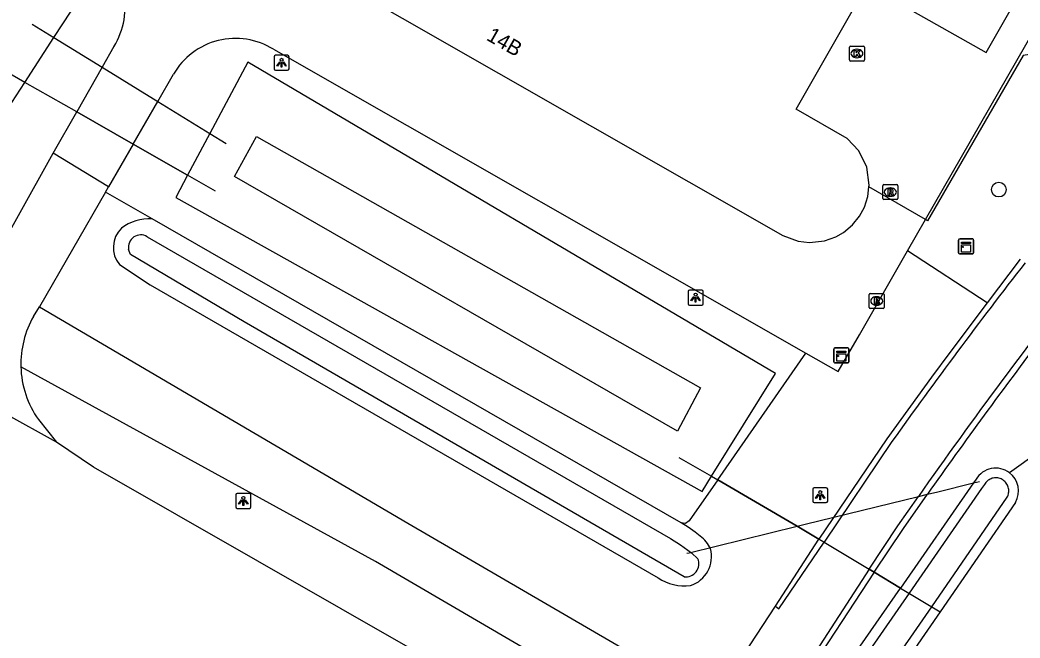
# Model space of a CAD drawing. Extents: x 157154 to 159278, y 385000 to 386650.
# Drawn here: x 158011.3 to 158077.8, y 385589.4 to 385630.5 of the extents above; entities that cross this region are included whole.
import ezdxf

# ---------------------------------------------------------------- set-up
doc = ezdxf.new("R2010")
doc.units = 0
for name, color, linetype in [('IMGEO_Boom', 7, 'Continuous'), ('IMGEO_Duiker', 7, 'Continuous'), ('IMGEO_Gemengd_bos', 7, 'Continuous'), ('IMGEO_Groenvoorziening', 7, 'Continuous'), ('IMGEO_Hek', 7, 'Continuous'), ('IMGEO_Kast', 7, 'Continuous'), ('IMGEO_Kolk', 7, 'Continuous'), ('IMGEO_Lichtpunt', 7, 'Continuous'), ('IMGEO_Pand', 7, 'Continuous'), ('IMGEO_Pand_nummerreeks', 7, 'Continuous'), ('IMGEO_Rijbaan_lokaal_gesloten', 7, 'Continuous'), ('IMGEO_Rijbaan_lokaal_open', 7, 'Continuous'), ('IMGEO_Rioolput', 7, 'Continuous'), ('IMGEO_Voetpad_halfverhard', 7, 'Continuous'), ('IMGEO_Waterloop', 7, 'Continuous')]:
    doc.layers.add(name, color=color, linetype=linetype)

msp = doc.modelspace()

# ---------------------------------------------------------------- linework, layer by layer
at = {"layer": 'IMGEO_Boom'}
msp.add_circle((158076.402, 385619.217), 0.489, dxfattribs=at)
at = {"layer": 'IMGEO_Duiker'}
for points in [[(158012.125, 385630.223), (158013.569, 385629.334), (158016.772, 385627.362), (158020.477, 385625.081), (158023.936, 385622.951), (158025.015, 385622.287)], [(158055.652, 385595.024), (158055.813, 385595.064), (158062.981, 385596.824), (158063.519, 385596.956), (158071.054, 385598.806), (158071.653, 385598.953), (158072.34, 385599.121), (158074.721, 385599.706), (158075.106, 385599.801)]]:
    msp.add_lwpolyline(points, dxfattribs=at)
at = {"layer": 'IMGEO_Gemengd_bos'}
for points in [[(158079.068, 385601.764), (158077.107, 385600.387)], [(158077.51, 385598.412), (158072.5, 385591.137), (158069.332, 385586.536)]]:
    msp.add_lwpolyline(points, dxfattribs=at)
msp.add_arc((158076.194, 385599.172), 1.52, 329.99375, 53.07208, dxfattribs=at)
at = {"layer": 'IMGEO_Groenvoorziening'}
for points in [[(158011.632, 385626.355), (158013.569, 385629.334), (158015.817, 385632.794), (157989.182, 385649.104), (157986.479, 385644.339), (157984.951, 385641.645)], [(157984.951, 385641.645), (157984.205, 385640.33), (158010.758, 385625.009), (158011.632, 385626.355)], [(158057.292, 385600.148), (158061.545, 385606.996), (158026.459, 385627.693), (158023.936, 385622.951), (158022.457, 385620.171)], [(158015.084, 385624.387), (158011.632, 385626.355)], [(158018.84, 385622.24), (158022.457, 385620.171)], [(158022.457, 385620.171), (158021.671, 385618.693), (158056.667, 385599.141), (158057.292, 385600.148)], [(158020.095, 385617.28), (158017.005, 385619.056)], [(158055.272, 385597.06), (158020.095, 385617.28)], [(158075.616, 385611.68), (158070.334, 385615.14)], [(158017.917, 385614.231), (158019.955, 385612.877), (158053.749, 385593.389)], [(158057.709, 385599.905), (158063.557, 385608.346)], [(158057.292, 385600.148), (158057.709, 385599.905)], [(158074.889, 385599.949), (158074.721, 385599.706), (158069.869, 385592.715)], [(158057.709, 385599.905), (158055.819, 385597.177), (158055.568, 385597.014), (158055.272, 385597.06)], [(158064.439, 385595.971), (158062.981, 385596.824), (158057.709, 385599.905)], [(158056.548, 385596.163), (158056.207, 385596.433), (158055.744, 385596.755), (158055.272, 385597.06)], [(158069.869, 385592.715), (158068.119, 385593.764)], [(158066.272, 385587.531), (158069.869, 385592.715)]]:
    msp.add_lwpolyline(points, dxfattribs=at)
for centre, radius, start, end in [((158019.932, 385614.19), 3.094, 86.98518, 127.46425), ((158019.322, 385615.365), 1.806, 134.80152, 218.89401), ((158076.194, 385599.174), 1.518, 53.04216, 149.29938), ((158055.244, 385594.407), 2.187, 25.18638, 53.39244), ((158055.259, 385594.807), 2.035, 288.01617, 15.12492), ((158055.537, 385596.102), 3.249, 236.61846, 276.20576)]:
    msp.add_arc(centre, radius, start, end, dxfattribs=at)
at = {"layer": 'IMGEO_Hek'}
for points in [[(158107.581, 385655.617), (158092.18, 385630.38), (158078.029, 385628.133), (158071.663, 385617.141), (158071.527, 385617.22)], [(158011.632, 385626.355), (158009.358, 385627.651)], [(158015.084, 385624.387), (158011.632, 385626.355)], [(158018.84, 385622.24), (158015.084, 385624.387)], [(158022.457, 385620.171), (158018.84, 385622.24)], [(158024.305, 385619.114), (158022.457, 385620.171)], [(158071.527, 385617.22), (158067.767, 385619.409)], [(158055.128, 385601.396), (158057.292, 385600.148)], [(158057.292, 385600.148), (158057.709, 385599.905)], [(158057.709, 385599.905), (158062.981, 385596.824)], [(158062.981, 385596.824), (158064.439, 385595.971)], [(158064.439, 385595.971), (158064.776, 385595.769)], [(158064.776, 385595.769), (158067.772, 385593.973)], [(158067.772, 385593.973), (158068.119, 385593.764)], [(158068.119, 385593.764), (158069.869, 385592.715)], [(158069.869, 385592.715), (158072.5, 385591.137)]]:
    msp.add_lwpolyline(points, dxfattribs=at)
at = {"layer": 'IMGEO_Kast'}
for p, q in [((158073.797, 385615.94), (158074.638, 385615.94)), ((158074.638, 385615.94), (158073.797, 385615.94)), ((158073.722, 385615.015), (158073.722, 385615.856)), ((158073.722, 385615.856), (158073.722, 385615.015)), ((158074.722, 385615.865), (158074.722, 385615.024)), ((158074.722, 385615.024), (158074.722, 385615.865)), ((158074.647, 385614.94), (158073.806, 385614.94)), ((158073.806, 385614.94), (158074.647, 385614.94)), ((158065.424, 385607.764), (158065.424, 385608.605)), ((158065.424, 385608.605), (158065.424, 385607.764)), ((158065.499, 385608.689), (158066.34, 385608.689)), ((158066.34, 385608.689), (158065.499, 385608.689)), ((158066.424, 385608.614), (158066.424, 385607.773)), ((158066.424, 385607.773), (158066.424, 385608.614)), ((158066.349, 385607.689), (158065.508, 385607.689)), ((158065.508, 385607.689), (158066.349, 385607.689))]:
    msp.add_line(p, q, dxfattribs=at)
for points in [[(158073.917, 385615.73), (158074.517, 385615.73), (158074.517, 385615.645), (158073.917, 385615.645), (158073.917, 385615.73)], [(158073.917, 385615.555), (158074.517, 385615.555), (158074.517, 385615.066), (158073.917, 385615.066), (158073.917, 385615.555)], [(158065.619, 385608.479), (158066.219, 385608.479), (158066.219, 385608.394), (158065.619, 385608.394), (158065.619, 385608.479)], [(158065.619, 385608.304), (158066.219, 385608.304), (158066.219, 385607.815), (158065.619, 385607.815), (158065.619, 385608.304)]]:
    msp.add_lwpolyline(points, dxfattribs=at)
for centre in [(158074.001, 385615.404), (158065.703, 385608.153)]:
    msp.add_circle(centre, 0.0377, dxfattribs=at)
for centre, start, end in [((158073.8, 385615.862), 92.4484, 184.28452), ((158073.8, 385615.862), 92.4484, 184.28452), ((158074.644, 385615.862), 2.4484, 94.28452), ((158074.644, 385615.862), 2.4484, 94.28452), ((158073.8, 385615.018), 182.4484, 274.28452), ((158073.8, 385615.018), 182.4484, 274.28452), ((158074.644, 385615.018), 272.4484, 4.28452), ((158074.644, 385615.018), 272.4484, 4.28452), ((158065.502, 385608.611), 92.4484, 184.28452), ((158065.502, 385608.611), 92.4484, 184.28452), ((158066.346, 385608.611), 2.4484, 94.28452), ((158066.346, 385608.611), 2.4484, 94.28452), ((158065.502, 385607.767), 182.4484, 274.28452), ((158065.502, 385607.767), 182.4484, 274.28452), ((158066.346, 385607.767), 272.4484, 4.28452), ((158066.346, 385607.767), 272.4484, 4.28452)]:
    msp.add_arc(centre, 0.0779, start, end, dxfattribs=at)
at = {"layer": 'IMGEO_Kolk'}
for p, q in [((158066.465, 385627.846), (158066.465, 385628.698)), ((158066.54, 385628.772), (158067.392, 385628.772)), ((158066.953, 385628.552), (158066.978, 385628.552)), ((158067.466, 385628.698), (158067.466, 385627.846)), ((158066.976, 385627.992), (158066.951, 385627.992)), ((158067.392, 385627.772), (158066.54, 385627.772))]:
    msp.add_line(p, q, dxfattribs=at)
for points in [[(158066.465, 385627.846), (158066.465, 385628.698)], [(158066.54, 385628.772), (158067.392, 385628.772)], [(158067.466, 385628.698), (158067.466, 385627.846)], [(158066.786, 385628.472), (158066.909, 385628.472), (158066.909, 385628.321), (158067.039, 385628.472), (158067.203, 385628.472), (158067.057, 385628.321), (158067.21, 385628.072), (158067.058, 385628.072), (158066.973, 385628.236), (158066.909, 385628.169), (158066.909, 385628.072), (158066.786, 385628.072), (158066.786, 385628.472)], [(158067.392, 385627.772), (158066.54, 385627.772)]]:
    msp.add_lwpolyline(points, dxfattribs=at)
for centre, start, end in [((158066.542, 385628.696), 91.55205, 178.44795), ((158066.542, 385628.696), 91.55205, 178.44795), ((158067.39, 385628.696), 1.55205, 88.44795), ((158067.39, 385628.696), 1.55205, 88.44795), ((158066.542, 385627.848), 181.55205, 268.44795), ((158066.542, 385627.848), 181.55205, 268.44795), ((158067.39, 385627.848), 271.55205, 358.44795), ((158067.39, 385627.848), 271.55205, 358.44795)]:
    msp.add_arc(centre, 0.0765, start, end, dxfattribs=at)
for centre, major_axis, ratio, start_param, end_param in [((158066.952, 385628.272), (-0.387, 0.002), 0.722429, 4.712389, 7.853982), ((158066.977, 385628.272), (-0.39, 0.002), 0.717154, 1.570796, 4.712389)]:
    msp.add_ellipse(centre, major_axis=major_axis, ratio=ratio, start_param=start_param, end_param=end_param, dxfattribs=at)
at = {"layer": 'IMGEO_Lichtpunt'}
for p, q in [((158028.206, 385628.061), (158028.206, 385627.254)), ((158028.206, 385628.061), (158028.206, 385627.254)), ((158029.108, 385628.156), (158028.3, 385628.156)), ((158029.108, 385628.156), (158028.3, 385628.156)), ((158029.202, 385627.254), (158029.202, 385628.061)), ((158029.202, 385627.254), (158029.202, 385628.061)), ((158028.3, 385627.16), (158029.108, 385627.16)), ((158028.3, 385627.16), (158029.108, 385627.16)), ((158055.739, 385612.437), (158055.739, 385611.63)), ((158055.739, 385612.437), (158055.739, 385611.63)), ((158056.641, 385612.532), (158055.833, 385612.532)), ((158056.641, 385612.532), (158055.833, 385612.532)), ((158056.735, 385611.63), (158056.735, 385612.437)), ((158056.735, 385611.63), (158056.735, 385612.437)), ((158055.833, 385611.536), (158056.641, 385611.536)), ((158055.833, 385611.536), (158056.641, 385611.536)), ((158064.024, 385599.296), (158064.024, 385598.489)), ((158064.024, 385599.296), (158064.024, 385598.489)), ((158064.926, 385599.391), (158064.118, 385599.391)), ((158064.926, 385599.391), (158064.118, 385599.391)), ((158065.02, 385598.489), (158065.02, 385599.296)), ((158065.02, 385598.489), (158065.02, 385599.296)), ((158025.662, 385598.914), (158025.662, 385598.107)), ((158025.662, 385598.914), (158025.662, 385598.107)), ((158026.564, 385599.009), (158025.756, 385599.009)), ((158026.564, 385599.009), (158025.756, 385599.009)), ((158026.658, 385598.107), (158026.658, 385598.914)), ((158026.658, 385598.107), (158026.658, 385598.914)), ((158025.756, 385598.013), (158026.564, 385598.013)), ((158025.756, 385598.013), (158026.564, 385598.013)), ((158064.118, 385598.395), (158064.926, 385598.395)), ((158064.118, 385598.395), (158064.926, 385598.395))]:
    msp.add_line(p, q, dxfattribs=at)
for points in [[(158028.58, 385627.725), (158028.619, 385627.697), (158028.431, 385627.435), (158028.393, 385627.462), (158028.58, 385627.725)], [(158028.682, 385627.677), (158028.729, 385627.677), (158028.729, 385627.355), (158028.682, 385627.355), (158028.682, 385627.677)], [(158028.792, 385627.697), (158028.83, 385627.724), (158029.017, 385627.462), (158028.978, 385627.434), (158028.792, 385627.697)], [(158056.113, 385612.101), (158056.152, 385612.073), (158055.964, 385611.811), (158055.926, 385611.838), (158056.113, 385612.101)], [(158056.215, 385612.053), (158056.262, 385612.053), (158056.262, 385611.731), (158056.215, 385611.731), (158056.215, 385612.053)], [(158056.325, 385612.073), (158056.363, 385612.1), (158056.55, 385611.838), (158056.511, 385611.81), (158056.325, 385612.073)], [(158064.398, 385598.96), (158064.437, 385598.932), (158064.249, 385598.67), (158064.211, 385598.697), (158064.398, 385598.96)], [(158064.5, 385598.912), (158064.547, 385598.912), (158064.547, 385598.59), (158064.5, 385598.59), (158064.5, 385598.912)], [(158064.61, 385598.932), (158064.648, 385598.959), (158064.835, 385598.697), (158064.796, 385598.669), (158064.61, 385598.932)], [(158026.036, 385598.578), (158026.075, 385598.55), (158025.887, 385598.288), (158025.849, 385598.315), (158026.036, 385598.578)], [(158026.138, 385598.53), (158026.185, 385598.53), (158026.185, 385598.208), (158026.138, 385598.208), (158026.138, 385598.53)], [(158026.248, 385598.55), (158026.286, 385598.577), (158026.473, 385598.315), (158026.434, 385598.287), (158026.248, 385598.55)]]:
    msp.add_lwpolyline(points, dxfattribs=at)
for centre in [(158028.705, 385627.859), (158056.238, 385612.235), (158026.161, 385598.712), (158064.523, 385599.094)]:
    msp.add_circle(centre, 0.0994, dxfattribs=at)
for centre, start, end in [((158028.3, 385628.061), 90, 180), ((158028.3, 385628.061), 90, 180), ((158029.108, 385628.061), 0, 90), ((158029.108, 385628.061), 0, 90), ((158028.3, 385627.254), 180, 270), ((158028.3, 385627.254), 180, 270), ((158029.108, 385627.254), 270, 0), ((158029.108, 385627.254), 270, 360), ((158055.833, 385612.437), 90, 180), ((158055.833, 385612.437), 90, 180), ((158056.641, 385612.437), 0, 90), ((158056.641, 385612.437), 0, 90), ((158055.833, 385611.63), 180, 270), ((158055.833, 385611.63), 180, 270), ((158056.641, 385611.63), 270, 0), ((158056.641, 385611.63), 270, 360), ((158064.118, 385599.296), 90, 180), ((158064.118, 385599.296), 90, 180), ((158064.926, 385599.296), 0, 90), ((158064.926, 385599.296), 0, 90), ((158025.756, 385598.914), 90, 180), ((158025.756, 385598.914), 90, 180), ((158026.564, 385598.914), 0, 90), ((158026.564, 385598.914), 0, 90), ((158025.756, 385598.107), 180, 270), ((158025.756, 385598.107), 180, 270), ((158026.564, 385598.107), 270, 0), ((158026.564, 385598.107), 270, 360), ((158064.118, 385598.489), 180, 270), ((158064.118, 385598.489), 180, 270), ((158064.926, 385598.489), 270, 0), ((158064.926, 385598.489), 270, 360)]:
    msp.add_arc(centre, 0.0946, start, end, dxfattribs=at)
at = {"layer": 'IMGEO_Pand'}
msp.add_lwpolyline([(158030.479, 385634.218), (158062.033, 385616.173), (158063.047, 385615.793), (158063.813, 385615.701), (158064.804, 385615.809), (158065.563, 385616.078), (158066.08, 385616.374), (158066.672, 385616.87), (158067.134, 385617.442), (158067.466, 385618.058), (158067.691, 385618.757), (158067.767, 385619.409), (158067.78, 385619.524), (158067.616, 385620.709), (158067.1, 385621.789), (158066.322, 385622.626), (158062.934, 385624.573), (158066.908, 385631.548)], dxfattribs=at)
at = {"layer": 'IMGEO_Rijbaan_lokaal_gesloten'}
for points in [[(158013.742, 385602.423), (157999.976, 385610.05)], [(158049.13, 385581.903), (158016.204, 385600.757), (158013.742, 385602.423)], [(158069.297, 385602.46), (158064.776, 385595.769)], [(158067.772, 385593.973), (158069.689, 385596.845), (158071.054, 385598.806)], [(158061.551, 385591.514), (158061.782, 385591.338), (158064.776, 385595.769)], [(158064.776, 385595.769), (158067.772, 385593.973)], [(158067.772, 385593.973), (158065, 385589.687), (158063.017, 385586.603)], [(158059.017, 385587.642), (158061.551, 385591.514)]]:
    msp.add_lwpolyline(points, dxfattribs=at)
for centre, radius, start, end in [((158358.836, 385396.209), 355.489, 142.14791, 144.53612), ((158360.951, 385395.616), 354.015, 141.90619, 144.97328)]:
    msp.add_arc(centre, radius, start, end, dxfattribs=at)
at = {"layer": 'IMGEO_Rijbaan_lokaal_open'}
for points in [[(158070.334, 385615.14), (158071.527, 385617.22), (158097.006, 385661.638)], [(158079.251, 385634.83), (158072.997, 385638.374), (158069.316, 385631.879), (158075.57, 385628.335), (158079.251, 385634.83)], [(158017.548, 385628.729), (158016.772, 385627.362), (158015.084, 385624.387)], [(158028.159, 385628.561), (158063.557, 385608.346)], [(158018.84, 385622.24), (158020.477, 385625.081), (158021.521, 385626.893)], [(158013.524, 385621.639), (158015.084, 385624.387)], [(158015.084, 385624.387), (158018.84, 385622.24)], [(158018.84, 385622.24), (158017.201, 385619.396)], [(158008.871, 385613.351), (158013.524, 385621.639)], [(158017.201, 385619.396), (158013.524, 385621.639)], [(158017.005, 385619.056), (158017.201, 385619.396)], [(158017.005, 385619.056), (158012.603, 385611.42)], [(158063.557, 385608.346), (158065.725, 385607.108), (158067.125, 385609.548), (158068.108, 385611.262), (158070.334, 385615.14)], [(158077.809, 385614.598), (158075.616, 385611.68)], [(158012.208, 385610.783), (158012.603, 385611.42)], [(158075.616, 385611.68), (158073.142, 385608.386), (158071.926, 385606.734), (158068.96, 385602.642), (158064.439, 385595.971)], [(158012.53, 385603.916), (158013.742, 385602.423)], [(158068.119, 385593.764), (158070.068, 385596.684), (158071.653, 385598.953)], [(158061.551, 385591.514), (158064.439, 385595.971)], [(158064.776, 385595.769), (158064.439, 385595.971)], [(158068.119, 385593.764), (158067.772, 385593.973)], [(158068.119, 385593.764), (158063.347, 385586.486), (158063.017, 385586.603)]]:
    msp.add_lwpolyline(points, dxfattribs=at)
for centre, radius, start, end in [((158013.397, 385631.327), 4.897, 327.95344, 58.12743), ((158025.643, 385624.532), 4.75, 58.0113, 150.19925), ((158017.794, 385607.604), 6.427, 150.35666, 181.47412), ((158370.981, 385388.124), 366.124, 142.81608, 144.84142), ((158017.798, 385607.605), 6.432, 181.47911, 215.00003)]:
    msp.add_arc(centre, radius, start, end, dxfattribs=at)
at = {"layer": 'IMGEO_Rioolput'}
for p, q in [((158068.686, 385618.629), (158068.686, 385619.481)), ((158068.761, 385619.555), (158069.613, 385619.555)), ((158069.174, 385619.335), (158069.199, 385619.335)), ((158069.687, 385619.481), (158069.687, 385618.629)), ((158069.613, 385618.555), (158068.761, 385618.555)), ((158069.197, 385618.775), (158069.172, 385618.775)), ((158067.779, 385611.385), (158067.779, 385612.237)), ((158067.854, 385612.311), (158068.706, 385612.311)), ((158068.267, 385612.091), (158068.292, 385612.091)), ((158068.78, 385612.237), (158068.78, 385611.385)), ((158068.706, 385611.311), (158067.854, 385611.311)), ((158068.29, 385611.531), (158068.265, 385611.531))]:
    msp.add_line(p, q, dxfattribs=at)
for points in [[(158068.686, 385618.629), (158068.686, 385619.481)], [(158068.761, 385619.555), (158069.613, 385619.555)], [(158069.275, 385619.253), (158069.023, 385619.255), (158069.023, 385618.855)], [(158069.687, 385619.481), (158069.687, 385618.629)], [(158069.613, 385618.555), (158068.761, 385618.555)], [(158069.023, 385618.855), (158069.147, 385618.855), (158069.147, 385619.017), (158069.158, 385619.017)], [(158069.201, 385619.174), (158069.147, 385619.174), (158069.147, 385619.093)], [(158069.147, 385619.093), (158069.199, 385619.093)], [(158069.205, 385618.988), (158069.276, 385618.855), (158069.416, 385618.855), (158069.351, 385618.981)], [(158067.779, 385611.385), (158067.779, 385612.237)], [(158067.854, 385612.311), (158068.706, 385612.311)], [(158068.368, 385612.009), (158068.116, 385612.011), (158068.116, 385611.611)], [(158068.294, 385611.93), (158068.24, 385611.93), (158068.24, 385611.849)], [(158068.78, 385612.237), (158068.78, 385611.385)], [(158068.706, 385611.311), (158067.854, 385611.311)], [(158068.116, 385611.611), (158068.24, 385611.611), (158068.24, 385611.773), (158068.251, 385611.773)], [(158068.24, 385611.849), (158068.292, 385611.849)], [(158068.298, 385611.744), (158068.369, 385611.611), (158068.509, 385611.611), (158068.444, 385611.737)]]:
    msp.add_lwpolyline(points, dxfattribs=at)
for centre, radius, start, end in [((158068.763, 385619.479), 0.0765, 91.55205, 178.44795), ((158068.763, 385619.479), 0.0765, 91.55205, 178.44795), ((158069.274, 385619.143), 0.109, 350.36119, 89.41601), ((158069.611, 385619.479), 0.0765, 1.55205, 88.44795), ((158069.611, 385619.479), 0.0765, 1.55205, 88.44795), ((158068.763, 385618.631), 0.0765, 181.55205, 268.44795), ((158068.763, 385618.631), 0.0765, 181.55205, 268.44795), ((158069.157, 385618.964), 0.0533, 26.02933, 88.69889), ((158069.183, 385619.282), 0.19, 274.7715, 282.96867), ((158069.207, 385619.078), 0.0964, 77.00612, 93.18647), ((158069.221, 385619.135), 0.0378, 276.66336, 79.67722), ((158069.272, 385619.143), 0.112, 277.58423, 350.98172), ((158069.256, 385618.928), 0.108, 29.51342, 73.79051), ((158069.611, 385618.631), 0.0765, 271.55205, 358.44795), ((158069.611, 385618.631), 0.0765, 271.55205, 358.44795), ((158067.856, 385612.235), 0.0765, 91.55205, 178.44795), ((158067.856, 385612.235), 0.0765, 91.55205, 178.44795), ((158068.3, 385611.834), 0.0964, 77.00612, 93.18647), ((158068.314, 385611.891), 0.0378, 276.66336, 79.67722), ((158068.367, 385611.899), 0.109, 350.36119, 89.41601), ((158068.704, 385612.235), 0.0765, 1.55205, 88.44795), ((158068.704, 385612.235), 0.0765, 1.55205, 88.44795), ((158067.856, 385611.387), 0.0765, 181.55205, 268.44795), ((158067.856, 385611.387), 0.0765, 181.55205, 268.44795), ((158068.25, 385611.72), 0.0533, 26.02933, 88.69889), ((158068.276, 385612.038), 0.19, 274.7715, 282.96867), ((158068.365, 385611.899), 0.112, 277.58423, 350.98172), ((158068.349, 385611.684), 0.108, 29.51342, 73.79051), ((158068.704, 385611.387), 0.0765, 271.55205, 358.44795), ((158068.704, 385611.387), 0.0765, 271.55205, 358.44795)]:
    msp.add_arc(centre, radius, start, end, dxfattribs=at)
for centre, major_axis, ratio, start_param, end_param in [((158069.173, 385619.055), (-0.387, 0.002), 0.722429, 4.712389, 7.853982), ((158069.198, 385619.055), (-0.39, 0.002), 0.717154, 1.570796, 4.712389), ((158068.266, 385611.811), (-0.387, 0.002), 0.722429, 4.712389, 7.853982), ((158068.291, 385611.811), (-0.39, 0.002), 0.717154, 1.570796, 4.712389)]:
    msp.add_ellipse(centre, major_axis=major_axis, ratio=ratio, start_param=start_param, end_param=end_param, dxfattribs=at)
at = {"layer": 'IMGEO_Voetpad_halfverhard'}
for points in [[(158012.603, 385611.42), (158037.098, 385597.025), (158056.935, 385585.476)], [(158053.652, 385583.548), (158034.946, 385594.473), (158011.369, 385607.439)]]:
    msp.add_lwpolyline(points, dxfattribs=at)
at = {"layer": 'IMGEO_Waterloop'}
for points in [[(158025.564, 385620.088), (158027.038, 385622.752), (158056.562, 385606.034), (158055.032, 385603.144), (158025.564, 385620.088)], [(158019.77, 385616.084), (158054.563, 385596.008), (158055.23, 385595.591), (158055.959, 385595.065), (158056.382, 385594.667)], [(158018.654, 385614.893), (158018.532, 385615.243)], [(158055.472, 385593.454), (158026.215, 385610.416), (158018.654, 385614.893)], [(158076.956, 385598.761), (158076.99, 385598.828), (158077.017, 385598.898), (158077.039, 385598.971), (158077.054, 385599.045), (158077.063, 385599.12), (158077.065, 385599.195), (158077.06, 385599.271), (158077.049, 385599.345), (158077.031, 385599.419), (158077.007, 385599.49), (158076.977, 385599.559), (158076.941, 385599.626), (158076.9, 385599.689), (158076.853, 385599.748), (158076.801, 385599.803), (158076.744, 385599.853), (158076.684, 385599.898), (158076.619, 385599.937), (158076.552, 385599.971), (158076.481, 385599.998), (158076.409, 385600.02), (158076.335, 385600.035), (158076.26, 385600.044), (158076.185, 385600.046), (158076.109, 385600.041), (158076.035, 385600.03), (158075.961, 385600.012), (158075.89, 385599.988), (158075.82, 385599.958), (158075.754, 385599.922), (158075.691, 385599.88), (158075.632, 385599.834), (158075.577, 385599.782), (158075.527, 385599.725), (158075.482, 385599.664), (158075.443, 385599.6), (158075.259, 385599.334), (158070.429, 385592.379), (158066.816, 385587.168)], [(158068.795, 385586.909), (158071.94, 385591.473), (158076.956, 385598.761)]]:
    msp.add_lwpolyline(points, dxfattribs=at)
for centre, radius, start, end in [((158019.334, 385615.393), 0.816, 57.76037, 190.61785), ((158055.567, 385594.33), 0.881, 263.789, 22.45609)]:
    msp.add_arc(centre, radius, start, end, dxfattribs=at)

# ---------------------------------------------------------------- texts
at = {"layer": 'IMGEO_Pand_nummerreeks'}
msp.add_text('14B', height=1, rotation=330.23484, dxfattribs=at).set_placement((158042.261, 385629.208))

doc.saveas('drawing.dxf')
